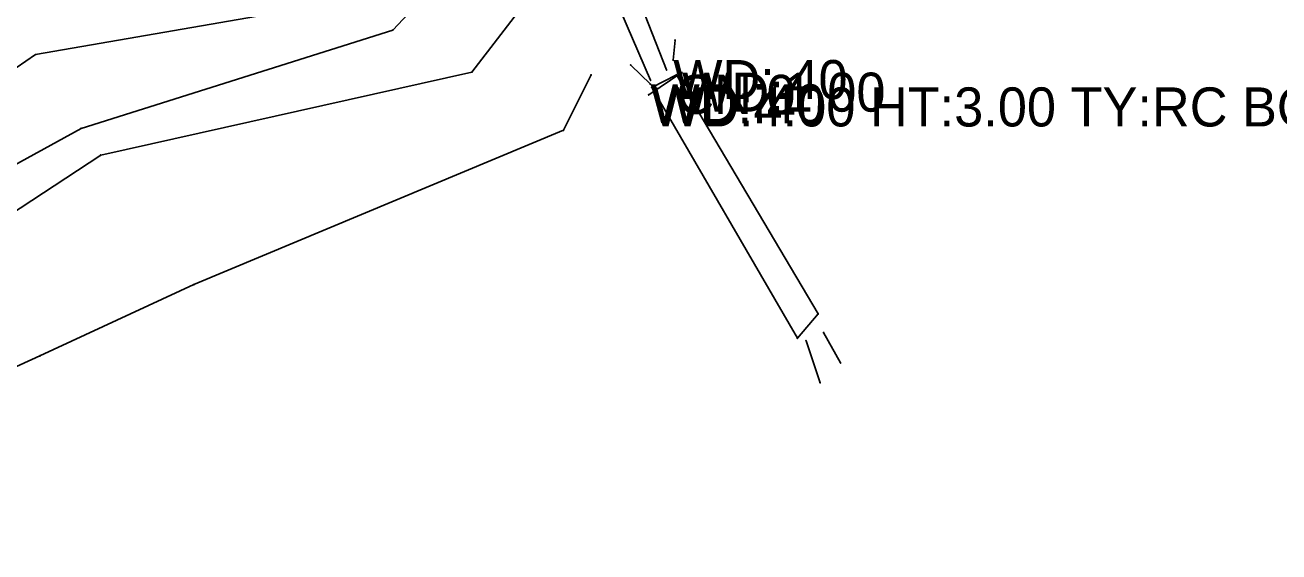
# Model space of a CAD drawing. Extents: x 1419505 to 1434054, y 1956910 to 1968644.
# Drawn here: x 1421906.9 to 1422067.1, y 1958176.2 to 1958243.6 of the extents above; entities that cross this region are included whole.
import ezdxf

# ---------------------------------------------------------------- set-up
doc = ezdxf.new("R2010")
doc.units = 0
for name, color, linetype in [('S_BREAKLINE', 7, 'Continuous'), ('S_CROSS_DRAIN', 7, 'Continuous'), ('S_CROSS_DRAIN_ANNOT', 7, 'Continuous'), ('S_DITCHLINE', 7, 'Continuous'), ('S_DRG_PT_SYM', 7, 'Continuous'), ('S_GRD_PT_SYM', 7, 'Continuous'), ('S_HEADWALL', 7, 'Continuous'), ('S_HEADWALL_ANNOT', 7, 'Continuous'), ('S_MSC_PT_SYM', 7, 'Continuous'), ('S_WALL', 7, 'Continuous'), ('S_WALL_ANNOT', 7, 'Continuous')]:
    doc.layers.add(name, color=color, linetype=linetype)

msp = doc.modelspace()

# ---------------------------------------------------------------- linework, layer by layer
at = {"layer": 'S_BREAKLINE'}
for p, q in [((1421953.8624, 1958242.9624), (1421967.2182, 1958257.3113)), ((1421908.1844, 1958239.8192), (1421949.3751, 1958247.0146)), ((1421914.0198, 1958230.3826), (1421953.8624, 1958242.9624)), ((1421878.1265, 1958219.1358), (1421908.1844, 1958239.8192)), ((1421975.6758, 1958230.1545), (1421979.191, 1958237.221)), ((1421883.6178, 1958213.5965), (1421914.0198, 1958230.3826)), ((1421928.4487, 1958210.4123), (1421975.6758, 1958230.1545)), ((1421908.7594, 1958201.2967), (1421928.4487, 1958210.4123)), ((1421854.1559, 1958176.2071), (1421908.7594, 1958201.2967))]:
    msp.add_line(p, q, dxfattribs=at)
at = {"layer": 'S_CROSS_DRAIN'}
for p, q in [((1421986.9635, 1958235.6309), (1421990.0937, 1958237.241)), ((1421990.0937, 1958237.241), (1422008.2199, 1958206.667)), ((1422005.5597, 1958203.5498), (1421986.9635, 1958235.6309)), ((1422008.2199, 1958206.667), (1422005.5597, 1958203.5498))]:
    msp.add_line(p, q, dxfattribs=at)
at = {"layer": 'S_DITCHLINE'}
for p, q in [((1421963.978, 1958237.6), (1421974.4557, 1958251.2699)), ((1421984.2623, 1958249.5828), (1421988.8426, 1958237.869)), ((1421981.7942, 1958248.1677), (1421986.8055, 1958236.563)), ((1421916.5319, 1958226.9663), (1421963.978, 1958237.6)), ((1421889.8312, 1958209.4182), (1421916.5319, 1958226.9663)), ((1422008.9189, 1958204.2599), (1422011.0881, 1958200.3846)), ((1422006.6698, 1958203.2198), (1422008.4739, 1958197.8595))]:
    msp.add_line(p, q, dxfattribs=at)
at = {"layer": 'S_DRG_PT_SYM'}
for points in [[(1421990.0937, 1958237.241), (1421990.0937, 1958237.291), (1421990.0937, 1958237.241), (1421990.0437, 1958237.241), (1421990.0937, 1958237.241), (1421990.0937, 1958237.191), (1421990.0937, 1958237.241), (1421990.1437, 1958237.241)], [(1421986.9635, 1958235.6309), (1421986.9635, 1958235.6809), (1421986.9635, 1958235.6309), (1421986.9135, 1958235.6309), (1421986.9635, 1958235.6309), (1421986.9635, 1958235.5809), (1421986.9635, 1958235.6309), (1421987.0135, 1958235.6309)], [(1422008.2199, 1958206.667), (1422008.2199, 1958206.717), (1422008.2199, 1958206.667), (1422008.1699, 1958206.667), (1422008.2199, 1958206.667), (1422008.2199, 1958206.617), (1422008.2199, 1958206.667), (1422008.2699, 1958206.667)], [(1422005.5597, 1958203.5498), (1422005.5597, 1958203.5998), (1422005.5597, 1958203.5498), (1422005.5097, 1958203.5498), (1422005.5597, 1958203.5498), (1422005.5597, 1958203.4998), (1422005.5597, 1958203.5498), (1422005.6097, 1958203.5498)]]:
    msp.add_lwpolyline(points, dxfattribs=at)
at = {"layer": 'S_GRD_PT_SYM'}
for points in [[(1421953.8624, 1958242.9624), (1421953.8624, 1958243.0124), (1421953.8624, 1958242.9624), (1421953.8124, 1958242.9624), (1421953.8624, 1958242.9624), (1421953.8624, 1958242.9124), (1421953.8624, 1958242.9624), (1421953.9124, 1958242.9624)], [(1421908.1844, 1958239.8192), (1421908.1844, 1958239.8692), (1421908.1844, 1958239.8192), (1421908.1344, 1958239.8192), (1421908.1844, 1958239.8192), (1421908.1844, 1958239.7692), (1421908.1844, 1958239.8192), (1421908.2344, 1958239.8192)], [(1421963.978, 1958237.6), (1421963.978, 1958237.65), (1421963.978, 1958237.6), (1421963.928, 1958237.6), (1421963.978, 1958237.6), (1421963.978, 1958237.55), (1421963.978, 1958237.6), (1421964.028, 1958237.6)], [(1421979.191, 1958237.221), (1421979.191, 1958237.271), (1421979.191, 1958237.221), (1421979.141, 1958237.221), (1421979.191, 1958237.221), (1421979.191, 1958237.171), (1421979.191, 1958237.221), (1421979.241, 1958237.221)], [(1421988.8426, 1958237.869), (1421988.8426, 1958237.919), (1421988.8426, 1958237.869), (1421988.7926, 1958237.869), (1421988.8426, 1958237.869), (1421988.8426, 1958237.819), (1421988.8426, 1958237.869), (1421988.8926, 1958237.869)], [(1421986.8055, 1958236.563), (1421986.8055, 1958236.613), (1421986.8055, 1958236.563), (1421986.7555, 1958236.563), (1421986.8055, 1958236.563), (1421986.8055, 1958236.513), (1421986.8055, 1958236.563), (1421986.8555, 1958236.563)], [(1421914.0198, 1958230.3826), (1421914.0198, 1958230.4326), (1421914.0198, 1958230.3826), (1421913.9698, 1958230.3826), (1421914.0198, 1958230.3826), (1421914.0198, 1958230.3326), (1421914.0198, 1958230.3826), (1421914.0698, 1958230.3826)], [(1421975.6758, 1958230.1545), (1421975.6758, 1958230.2045), (1421975.6758, 1958230.1545), (1421975.6258, 1958230.1545), (1421975.6758, 1958230.1545), (1421975.6758, 1958230.1045), (1421975.6758, 1958230.1545), (1421975.7258, 1958230.1545)], [(1421916.5319, 1958226.9663), (1421916.5319, 1958227.0163), (1421916.5319, 1958226.9663), (1421916.4819, 1958226.9663), (1421916.5319, 1958226.9663), (1421916.5319, 1958226.9163), (1421916.5319, 1958226.9663), (1421916.5819, 1958226.9663)], [(1421928.4487, 1958210.4123), (1421928.4487, 1958210.4623), (1421928.4487, 1958210.4123), (1421928.3987, 1958210.4123), (1421928.4487, 1958210.4123), (1421928.4487, 1958210.3623), (1421928.4487, 1958210.4123), (1421928.4987, 1958210.4123)], [(1422008.9189, 1958204.2599), (1422008.9189, 1958204.3099), (1422008.9189, 1958204.2599), (1422008.8689, 1958204.2599), (1422008.9189, 1958204.2599), (1422008.9189, 1958204.2099), (1422008.9189, 1958204.2599), (1422008.9689, 1958204.2599)], [(1422006.6698, 1958203.2198), (1422006.6698, 1958203.2698), (1422006.6698, 1958203.2198), (1422006.6198, 1958203.2198), (1422006.6698, 1958203.2198), (1422006.6698, 1958203.1698), (1422006.6698, 1958203.2198), (1422006.7198, 1958203.2198)], [(1421908.7594, 1958201.2967), (1421908.7594, 1958201.3467), (1421908.7594, 1958201.2967), (1421908.7094, 1958201.2967), (1421908.7594, 1958201.2967), (1421908.7594, 1958201.2467), (1421908.7594, 1958201.2967), (1421908.8094, 1958201.2967)], [(1422011.0881, 1958200.3846), (1422011.0881, 1958200.4346), (1422011.0881, 1958200.3846), (1422011.0381, 1958200.3846), (1422011.0881, 1958200.3846), (1422011.0881, 1958200.3346), (1422011.0881, 1958200.3846), (1422011.1381, 1958200.3846)], [(1422008.4739, 1958197.8595), (1422008.4739, 1958197.9095), (1422008.4739, 1958197.8595), (1422008.4239, 1958197.8595), (1422008.4739, 1958197.8595), (1422008.4739, 1958197.8095), (1422008.4739, 1958197.8595), (1422008.5239, 1958197.8595)]]:
    msp.add_lwpolyline(points, dxfattribs=at)
at = {"layer": 'S_HEADWALL'}
msp.add_line((1421990.8147, 1958237.528), (1421986.5575, 1958234.6838), dxfattribs=at)
at = {"layer": 'S_MSC_PT_SYM'}
for points in [[(1421989.9367, 1958241.6703), (1421989.9367, 1958241.7203), (1421989.9367, 1958241.6703), (1421989.8867, 1958241.6703), (1421989.9367, 1958241.6703), (1421989.9367, 1958241.6203), (1421989.9367, 1958241.6703), (1421989.9867, 1958241.6703)], [(1421989.6827, 1958239.1281), (1421989.6827, 1958239.1781), (1421989.6827, 1958239.1281), (1421989.6327, 1958239.1281), (1421989.6827, 1958239.1281), (1421989.6827, 1958239.0781), (1421989.6827, 1958239.1281), (1421989.7327, 1958239.1281)], [(1421984.2733, 1958238.4871), (1421984.2733, 1958238.5371), (1421984.2733, 1958238.4871), (1421984.2233, 1958238.4871), (1421984.2733, 1958238.4871), (1421984.2733, 1958238.4371), (1421984.2733, 1958238.4871), (1421984.3233, 1958238.4871)], [(1421990.8147, 1958237.528), (1421990.8147, 1958237.578), (1421990.8147, 1958237.528), (1421990.7647, 1958237.528), (1421990.8147, 1958237.528), (1421990.8147, 1958237.478), (1421990.8147, 1958237.528), (1421990.8647, 1958237.528)], [(1421986.7775, 1958236.0289), (1421986.7775, 1958236.0789), (1421986.7775, 1958236.0289), (1421986.7275, 1958236.0289), (1421986.7775, 1958236.0289), (1421986.7775, 1958235.9789), (1421986.7775, 1958236.0289), (1421986.8275, 1958236.0289)], [(1421986.5575, 1958234.6838), (1421986.5575, 1958234.7338), (1421986.5575, 1958234.6838), (1421986.5075, 1958234.6838), (1421986.5575, 1958234.6838), (1421986.5575, 1958234.6338), (1421986.5575, 1958234.6838), (1421986.6075, 1958234.6838)]]:
    msp.add_lwpolyline(points, dxfattribs=at)
at = {"layer": 'S_WALL'}
for p, q in [((1421989.6827, 1958239.1281), (1421989.9367, 1958241.6703)), ((1421986.7775, 1958236.0289), (1421984.2733, 1958238.4871))]:
    msp.add_line(p, q, dxfattribs=at)

# ---------------------------------------------------------------- texts
at = {"layer": 'S_CROSS_DRAIN_ANNOT'}
for s, p in [('CN:0', (1421990.0937, 1958232.241)), ('WD:4.00 HT:3.00 TY:RC BOX CN:0', (1421986.9635, 1958230.6309))]:
    msp.add_text(s, height=5, dxfattribs=at).set_placement(p)
at = {"layer": 'S_HEADWALL_ANNOT'}
msp.add_text('WD:1.00', height=5, dxfattribs=at).set_placement((1421990.8147, 1958232.528))
at = {"layer": 'S_WALL_ANNOT'}
for p in [(1421989.6827, 1958234.1281), (1421986.7775, 1958231.0289)]:
    msp.add_text('WD:.40', height=5, dxfattribs=at).set_placement(p)

doc.saveas('drawing.dxf')
